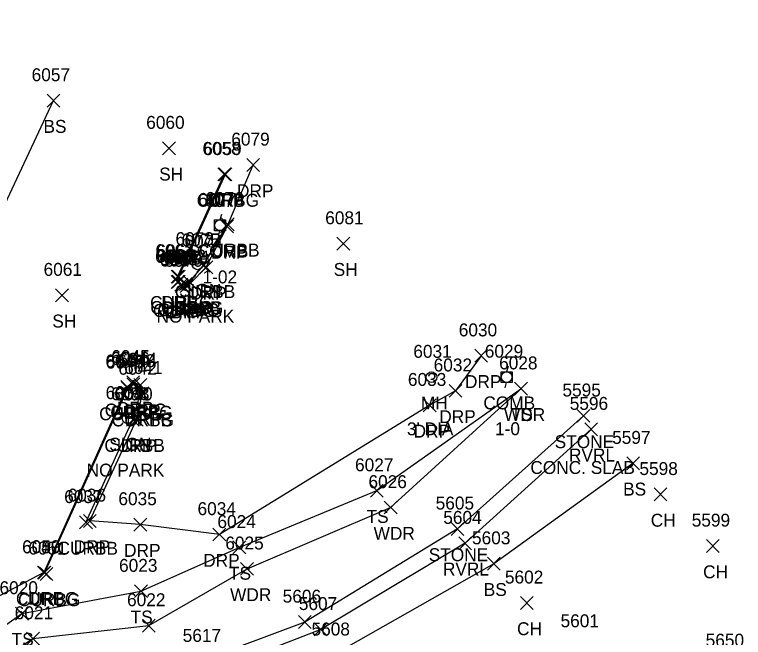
# Model space of a CAD drawing. Extents: x 1618146 to 1620418, y 640749 to 641927.
# Drawn here: x 1620082.5 to 1620195.4, y 641323.6 to 641420.1 of the extents above; entities that cross this region are included whole.
import ezdxf

# ---------------------------------------------------------------- set-up
doc = ezdxf.new("R2010")
doc.units = 0
for name, color, linetype in [('L_A', 7, 'Continuous'), ('L_C', 7, 'Continuous'), ('L_I', 7, 'Continuous'), ('L_TIC', 7, 'Continuous'), ('LASF', 7, 'Continuous'), ('LAWA', 7, 'Continuous'), ('LAWE', 7, 'Continuous'), ('LELB', 7, 'Continuous'), ('R_A', 7, 'Continuous'), ('R_I', 7, 'Continuous'), ('R_TIC', 7, 'Continuous'), ('RC', 7, 'Continuous'), ('RDP', 7, 'Continuous'), ('S_A', 7, 'Continuous'), ('S_C', 7, 'Continuous'), ('S_I', 7, 'Continuous'), ('SSGN', 7, 'Continuous'), ('U_A', 7, 'Continuous'), ('U_C', 7, 'Continuous'), ('U_I', 7, 'Continuous'), ('UP', 7, 'Continuous'), ('UUMH', 7, 'Continuous')]:
    doc.layers.add(name, color=color, linetype=linetype)

msp = doc.modelspace()

# ---------------------------------------------------------------- linework, layer by layer
at = {"layer": 'L_TIC'}
for points in [[(1620087.57, 641405.74), (1620089.57, 641407.74)], [(1620089.57, 641405.74), (1620087.57, 641407.74)], [(1620105.45, 641398.36), (1620107.45, 641400.36)], [(1620107.45, 641398.36), (1620105.45, 641400.36)], [(1620132.48, 641383.59), (1620134.48, 641385.59)], [(1620134.48, 641383.59), (1620132.48, 641385.59)], [(1620088.89, 641375.6), (1620090.89, 641377.6)], [(1620090.89, 641375.6), (1620088.89, 641377.6)], [(1620159.99, 641361.12), (1620161.99, 641363.12)], [(1620161.99, 641361.12), (1620159.99, 641363.12)], [(1620159.99, 641361.12), (1620161.99, 641363.12)], [(1620161.99, 641361.12), (1620159.99, 641363.12)], [(1620169.67, 641356.92), (1620171.67, 641358.92)], [(1620171.67, 641356.92), (1620169.67, 641358.92)], [(1620170.86, 641354.85), (1620172.86, 641356.85)], [(1620172.86, 641354.85), (1620170.86, 641356.85)], [(1620177.37, 641349.58), (1620179.37, 641351.58)], [(1620179.37, 641349.58), (1620177.37, 641351.58)], [(1620137.66, 641345.34), (1620139.66, 641347.34)], [(1620139.66, 641345.34), (1620137.66, 641347.34)], [(1620181.6, 641344.76), (1620183.6, 641346.76)], [(1620183.6, 641344.76), (1620181.6, 641346.76)], [(1620139.8, 641342.73), (1620141.8, 641344.73)], [(1620141.8, 641342.73), (1620139.8, 641344.73)], [(1620150.16, 641339.42), (1620152.16, 641341.42)], [(1620152.16, 641339.42), (1620150.16, 641341.42)], [(1620151.34, 641337.2), (1620153.34, 641339.2)], [(1620153.34, 641337.2), (1620151.34, 641339.2)], [(1620116.34, 641336.55), (1620118.34, 641338.55)], [(1620118.34, 641336.55), (1620116.34, 641338.55)], [(1620189.71, 641336.77), (1620191.71, 641338.77)], [(1620191.71, 641336.77), (1620189.71, 641338.77)], [(1620155.78, 641334.03), (1620157.78, 641336.03)], [(1620157.78, 641334.03), (1620155.78, 641336.03)], [(1620117.56, 641333.23), (1620119.56, 641335.23)], [(1620119.56, 641333.23), (1620117.56, 641335.23)], [(1620101.11, 641329.77), (1620103.11, 641331.77)], [(1620103.11, 641329.77), (1620101.11, 641331.77)], [(1620160.89, 641327.96), (1620162.89, 641329.96)], [(1620162.89, 641327.96), (1620160.89, 641329.96)], [(1620082.67, 641326.31), (1620084.67, 641328.31)], [(1620084.67, 641326.31), (1620082.67, 641328.31)], [(1620126.51, 641325), (1620128.51, 641327)], [(1620128.51, 641325), (1620126.51, 641327)], [(1620102.34, 641324.45), (1620104.34, 641326.45)], [(1620104.34, 641324.45), (1620102.34, 641326.45)], [(1620128.96, 641323.85), (1620130.96, 641325.85)], [(1620130.96, 641323.85), (1620128.96, 641325.85)], [(1620084.38, 641322.43), (1620086.38, 641324.43)], [(1620086.38, 641322.43), (1620084.38, 641324.43)]]:
    msp.add_lwpolyline(points, dxfattribs=at)
at = {"layer": 'LASF'}
msp.add_lwpolyline([(1620170.67, 641357.92), (1620151.16, 641340.42), (1620127.51, 641326), (1620111.32, 641319.92), (1620095.61, 641318.35), (1620069.66, 641305.45), (1620049.44, 641298.08), (1620030.95, 641301.74), (1620009.21, 641303.41), (1619992.86, 641294.85), (1619980.43, 641291.88)], dxfattribs=at)
at = {"layer": 'LAWA'}
msp.add_lwpolyline([(1620069.66, 641305.45), (1620057.71, 641308.73), (1620064.58, 641309.15), (1620072.37, 641314.79), (1620085.38, 641323.43), (1620103.34, 641325.45), (1620118.56, 641334.23), (1620140.8, 641343.73), (1620160.99, 641362.12)], dxfattribs=at)
at = {"layer": 'LAWE'}
msp.add_lwpolyline([(1620171.86, 641355.85), (1620152.34, 641338.2), (1620129.96, 641324.85), (1620111.93, 641317.84), (1620096.25, 641317.33), (1620096.2, 641316.75), (1620094.16, 641317.06), (1620094.28, 641315.29), (1620071.24, 641300.59), (1620050.39, 641293.63), (1620030.98, 641297.72), (1620009.6, 641296.43), (1619997.99, 641289.69), (1619969.13, 641278.68), (1619952.14, 641274.33), (1619935.16, 641265.54), (1619913.67, 641252.74)], dxfattribs=at)
at = {"layer": 'LELB'}
for points in [[(1620044.68, 641320.25), (1620056.71, 641339.91), (1620068.51, 641363.99), (1620079.85, 641388.24), (1620088.57, 641406.74)], [(1619998.22, 641324.34), (1620000.03, 641323.74), (1620010.58, 641317.4), (1620012.2, 641312.35), (1620021.85, 641309.22), (1620032.97, 641306.95), (1620046.8, 641309.77), (1620057.71, 641308.73), (1620071.27, 641318.53), (1620083.67, 641327.31), (1620102.11, 641330.77), (1620117.34, 641337.55), (1620138.66, 641346.34), (1620160.99, 641362.12)], [(1620178.37, 641350.58), (1620156.78, 641335.03), (1620131.93, 641320.91), (1620116.04, 641312.86), (1620100.67, 641308.52)]]:
    msp.add_lwpolyline(points, dxfattribs=at)
at = {"layer": 'R_TIC'}
for points in [[(1620118.5, 641395.77), (1620120.5, 641397.77)], [(1620120.5, 641395.77), (1620118.5, 641397.77)], [(1620114.02, 641394.33), (1620116.02, 641396.33)], [(1620116.02, 641394.33), (1620114.02, 641396.33)], [(1620114.17, 641394.3), (1620116.17, 641396.3)], [(1620116.17, 641394.3), (1620114.17, 641396.3)], [(1620114.46, 641386.26), (1620116.46, 641388.26)], [(1620116.46, 641386.26), (1620114.46, 641388.26)], [(1620114.55, 641386.58), (1620116.55, 641388.58)], [(1620116.55, 641386.58), (1620114.55, 641388.58)], [(1620110.77, 641380.16), (1620112.77, 641382.16)], [(1620112.77, 641380.16), (1620110.77, 641382.16)], [(1620111.24, 641379.92), (1620113.24, 641381.92)], [(1620113.24, 641379.92), (1620111.24, 641381.92)], [(1620106.77, 641378.49), (1620108.77, 641380.49)], [(1620108.77, 641378.49), (1620106.77, 641380.49)], [(1620106.95, 641378.46), (1620108.95, 641380.46)], [(1620108.95, 641378.46), (1620106.95, 641380.46)], [(1620106.97, 641377.7), (1620108.97, 641379.7)], [(1620108.97, 641377.7), (1620106.97, 641379.7)], [(1620108.63, 641377.65), (1620110.63, 641379.65)], [(1620110.63, 641377.65), (1620108.63, 641379.65)], [(1620108.63, 641377.65), (1620110.63, 641379.65)], [(1620110.63, 641377.65), (1620108.63, 641379.65)], [(1620106.8, 641377.63), (1620108.8, 641379.63)], [(1620108.8, 641377.63), (1620106.8, 641379.63)], [(1620107.38, 641377.24), (1620109.38, 641379.24)], [(1620109.38, 641377.24), (1620107.38, 641379.24)], [(1620107.47, 641377.04), (1620109.47, 641379.04)], [(1620109.47, 641377.04), (1620107.47, 641379.04)], [(1620108.07, 641377.35), (1620110.07, 641379.35)], [(1620110.07, 641377.35), (1620108.07, 641379.35)], [(1620108.21, 641377.01), (1620110.21, 641379.01)], [(1620110.21, 641377.01), (1620108.21, 641379.01)], [(1620108.8, 641377.49), (1620110.8, 641379.49)], [(1620110.8, 641377.49), (1620108.8, 641379.49)], [(1620153.82, 641366.23), (1620155.82, 641368.23)], [(1620155.82, 641366.23), (1620153.82, 641368.23)], [(1620099.91, 641362.1), (1620101.91, 641364.1)], [(1620101.91, 641362.1), (1620099.91, 641364.1)], [(1620099, 641361.41), (1620101, 641363.41)], [(1620101, 641361.41), (1620099, 641363.41)], [(1620099.06, 641361.24), (1620101.06, 641363.24)], [(1620101.06, 641361.24), (1620099.06, 641363.24)], [(1620099.92, 641361.82), (1620101.92, 641363.82)], [(1620101.92, 641361.82), (1620099.92, 641363.82)], [(1620100.78, 641361.46), (1620102.78, 641363.46)], [(1620102.78, 641361.46), (1620100.78, 641363.46)], [(1620101.03, 641361.68), (1620103.03, 641363.68)], [(1620103.03, 641361.68), (1620101.03, 641363.68)], [(1620149.85, 641360.8), (1620151.85, 641362.8)], [(1620151.85, 641360.8), (1620149.85, 641362.8)], [(1620101, 641360.29), (1620103, 641362.29)], [(1620103, 641360.29), (1620101, 641362.29)], [(1620101, 641360.29), (1620103, 641362.29)], [(1620103, 641360.29), (1620101, 641362.29)], [(1620101.33, 641360.4), (1620103.33, 641362.4)], [(1620103.33, 641360.4), (1620101.33, 641362.4)], [(1620145.86, 641358.56), (1620147.86, 641360.56)], [(1620147.86, 641358.56), (1620145.86, 641360.56)], [(1620099.86, 641356.34), (1620101.86, 641358.34)], [(1620101.86, 641356.34), (1620099.86, 641358.34)], [(1620100.45, 641356.31), (1620102.45, 641358.31)], [(1620102.45, 641356.31), (1620100.45, 641358.31)], [(1620092.6, 641340.42), (1620094.6, 641342.42)], [(1620094.6, 641340.42), (1620092.6, 641342.42)], [(1620093.2, 641340.65), (1620095.2, 641342.65)], [(1620095.2, 641340.65), (1620093.2, 641342.65)], [(1620101.01, 641340.09), (1620103.01, 641342.09)], [(1620103.01, 641340.09), (1620101.01, 641342.09)], [(1620113.27, 641338.55), (1620115.27, 641340.55)], [(1620115.27, 641338.55), (1620113.27, 641340.55)], [(1620086.09, 641332.66), (1620088.09, 641334.66)], [(1620088.09, 641332.66), (1620086.09, 641334.66)], [(1620086.17, 641332.63), (1620088.17, 641334.63)], [(1620088.17, 641332.63), (1620086.17, 641334.63)], [(1620086.48, 641332.45), (1620088.48, 641334.45)], [(1620088.48, 641332.45), (1620086.48, 641334.45)]]:
    msp.add_lwpolyline(points, dxfattribs=at)
at = {"layer": 'RC'}
for points in [[(1620115.17, 641395.3), (1620107.95, 641379.46), (1620107.97, 641378.7), (1620108.38, 641378.24), (1620109.07, 641378.35), (1620109.63, 641378.65)], [(1620109.63, 641378.65), (1620111.77, 641381.16), (1620115.55, 641387.58)], [(1620102, 641361.29), (1620101.78, 641362.46), (1620100.92, 641362.82), (1620100.06, 641362.24), (1620087.17, 641333.63), (1620087.48, 641333.45)], [(1620093.6, 641341.42), (1620100.86, 641357.34), (1620102, 641361.29)]]:
    msp.add_lwpolyline(points, dxfattribs=at)
at = {"layer": 'RDP'}
for points in [[(1620154.82, 641367.23), (1620150.85, 641361.8), (1620146.86, 641359.56), (1620114.27, 641339.55), (1620102.01, 641341.09), (1620094.2, 641341.65), (1620101.45, 641357.31), (1620102.33, 641361.4), (1620102.03, 641362.68), (1620100.91, 641363.1), (1620100, 641362.41), (1620087.09, 641333.66), (1620057.86, 641318.28), (1620044.68, 641320.25), (1620026.69, 641324.52), (1620013.64, 641332.89), (1620019.29, 641346.64), (1620028.94, 641364.44), (1620041.85, 641389.16), (1620058.65, 641420.05)], [(1620115.02, 641395.33), (1620107.77, 641379.49), (1620107.8, 641378.63), (1620108.47, 641378.04), (1620109.21, 641378.01), (1620109.8, 641378.49), (1620112.24, 641380.92), (1620115.46, 641387.26), (1620119.5, 641396.77)]]:
    msp.add_lwpolyline(points, dxfattribs=at)
at = {"layer": 'SSGN'}
for p, q in [((1620109.23, 641382.21), (1620112.57, 641382.21)), ((1620110.88, 641381.38), (1620110.88, 641381.38)), ((1620098.41, 641358.38), (1620101.74, 641358.38)), ((1620100.05, 641357.55), (1620100.05, 641357.55))]:
    msp.add_line(p, q, dxfattribs=at)
for centre in [(1620110.88, 641381.38), (1620100.05, 641357.55)]:
    msp.add_circle(centre, 0.833, dxfattribs=at)
at = {"layer": 'UP'}
for p, q in [((1620114.61, 641389.09), (1620114.36, 641388.26)), ((1620113.52, 641386.59), (1620113.52, 641388.26)), ((1620113.52, 641388.26), (1620115.19, 641388.26)), ((1620115.19, 641388.26), (1620115.19, 641386.59)), ((1620115.19, 641386.59), (1620113.52, 641386.59)), ((1620114.11, 641385.76), (1620114.36, 641386.59)), ((1620114.36, 641387.43), (1620114.36, 641387.43)), ((1620159.02, 641365.59), (1620158.77, 641364.76)), ((1620157.94, 641363.09), (1620157.94, 641364.76)), ((1620157.94, 641364.76), (1620159.6, 641364.76)), ((1620158.77, 641363.93), (1620158.77, 641363.93)), ((1620159.6, 641364.76), (1620159.6, 641363.09)), ((1620159.6, 641363.09), (1620157.94, 641363.09)), ((1620158.52, 641362.26), (1620158.77, 641363.09))]:
    msp.add_line(p, q, dxfattribs=at)
for centre in [(1620114.36, 641387.43), (1620158.77, 641363.93)]:
    msp.add_circle(centre, 0.833, dxfattribs=at)
at = {"layer": 'UUMH'}
for p, q in [((1620147.13, 641363.91), (1620147.13, 641363.91)), ((1620147.96, 641363.91), (1620147.96, 641363.91))]:
    msp.add_line(p, q, dxfattribs=at)
msp.add_circle((1620147.13, 641363.91), 0.833, dxfattribs=at)

# ---------------------------------------------------------------- texts
at = {"layer": 'L_A'}
for s, p in [('BS', (1620087.01, 641401.74)), ('SH', (1620104.94, 641394.36)), ('SH', (1620131.97, 641379.59)), ('SH', (1620088.38, 641371.6)), ('WDR', (1620158.35, 641357.12)), ('TS', (1620159.4, 641357.12)), ('STONE', (1620166.21, 641352.92)), ('RVRL', (1620168.43, 641350.85)), ('BS', (1620176.81, 641345.58)), ('TS', (1620137.07, 641341.34)), ('CH', (1620181.09, 641340.76)), ('WDR', (1620138.16, 641338.73)), ('STONE', (1620146.7, 641335.42)), ('TS', (1620115.75, 641332.55)), ('RVRL', (1620148.9, 641333.2)), ('CH', (1620189.2, 641332.77)), ('WDR', (1620115.92, 641329.23)), ('BS', (1620155.22, 641330.03)), ('TS', (1620100.52, 641325.77)), ('CH', (1620160.38, 641323.96)), ('TS', (1620082.08, 641322.31))]:
    msp.add_text(s, height=2, dxfattribs=at).set_placement(p)
at = {"layer": 'L_C'}
msp.add_text('CONC. SLAB', height=2, dxfattribs=at).set_placement((1620162.44, 641348.92))
at = {"layer": 'L_I'}
for s, p in [('6057', (1620085.18, 641409.74)), ('6060', (1620102.93, 641402.36)), ('6081', (1620130.66, 641387.59)), ('6061', (1620087.03, 641379.6)), ('6028', (1620157.6, 641365.12)), ('6028', (1620157.6, 641365.12)), ('5595', (1620167.41, 641360.92)), ('5596', (1620168.54, 641358.85)), ('5597', (1620175.11, 641353.58)), ('6027', (1620135.28, 641349.34)), ('5598', (1620179.34, 641348.76)), ('6026', (1620137.36, 641346.73)), ('5605', (1620147.77, 641343.42)), ('6024', (1620113.96, 641340.55)), ('5604', (1620148.95, 641341.2)), ('5599', (1620187.44, 641340.77)), ('6025', (1620115.18, 641337.23)), ('5603', (1620153.4, 641338.03)), ('6023', (1620098.72, 641333.77)), ('5602', (1620158.5, 641331.96)), ('6020', (1620080.2, 641330.31)), ('6022', (1620099.96, 641328.45)), ('5606', (1620124.07, 641329)), ('5607', (1620126.57, 641327.85)), ('6021', (1620082.56, 641326.43)), ('5601', (1620167.12, 641325.19)), ('5608', (1620128.54, 641323.91)), ('5617', (1620108.58, 641322.92)), ('5650', (1620189.6, 641322.19))]:
    msp.add_text(s, height=2, dxfattribs=at).set_placement(p)
at = {"layer": 'R_A'}
for s, p in [('DRP', (1620116.99, 641391.77)), ('CURBG', (1620110.75, 641390.3)), ('DRP', (1620112.51, 641390.33)), ('CURBB', (1620111.13, 641382.58)), ('DRP', (1620112.95, 641382.26)), ('CURBB', (1620107.36, 641376.16)), ('DRP', (1620109.73, 641375.92)), ('CURBG', (1620103.53, 641374.46)), ('DRP', (1620105.26, 641374.49)), ('CURBG', (1620103.56, 641373.7)), ('CURBG', (1620103.97, 641373.24)), ('CURBG', (1620104.65, 641373.35)), ('CURBG', (1620105.21, 641373.65)), ('CURBB', (1620105.21, 641373.65)), ('DRP', (1620105.29, 641373.63)), ('DRP', (1620107.29, 641373.49)), ('DRP', (1620105.96, 641373.04)), ('DRP', (1620106.7, 641373.01)), ('DRP', (1620152.31, 641362.23)), ('CURBG', (1620096.5, 641357.82)), ('CURBG', (1620097.36, 641357.46)), ('DRP', (1620097.49, 641357.41)), ('DRP', (1620098.39, 641358.1)), ('DRP', (1620099.52, 641357.68)), ('CURBG', (1620095.64, 641357.24)), ('CURBG', (1620097.58, 641356.29)), ('CURBB', (1620097.58, 641356.29)), ('DRP', (1620099.82, 641356.4)), ('DRP', (1620148.33, 641356.8)), ('DRP', (1620144.35, 641354.56)), ('CURBB', (1620096.45, 641352.34)), ('DRP', (1620098.94, 641352.31)), ('CURBB', (1620089.19, 641336.42)), ('DRP', (1620091.69, 641336.65)), ('DRP', (1620099.5, 641336.09)), ('DRP', (1620111.76, 641334.55)), ('CURBG', (1620082.75, 641328.63)), ('CURBG', (1620083.06, 641328.45)), ('DRP', (1620084.58, 641328.66))]:
    msp.add_text(s, height=2, dxfattribs=at).set_placement(p)
at = {"layer": 'R_I'}
for s, p in [('6079', (1620116.11, 641399.77)), ('6058', (1620111.64, 641398.33)), ('6059', (1620111.77, 641398.3)), ('6078', (1620112.07, 641390.26)), ('6076', (1620112.1, 641390.58)), ('6075', (1620108.39, 641384.16)), ('6074', (1620108.86, 641383.92)), ('6063', (1620104.34, 641382.49)), ('6064', (1620104.51, 641382.46)), ('6066', (1620104.31, 641381.63)), ('6065', (1620104.54, 641381.7)), ('6068', (1620104.95, 641381.24)), ('6067', (1620105.04, 641381.04)), ('6069', (1620105.63, 641381.35)), ('6070', (1620105.74, 641381.01)), ('6072', (1620106.24, 641381.65)), ('6072', (1620106.24, 641381.65)), ('6071', (1620106.98, 641381.49)), ('6030', (1620151.35, 641370.23)), ('6048', (1620096.61, 641365.41)), ('6047', (1620096.67, 641365.24)), ('6046', (1620097.48, 641365.82)), ('6045', (1620097.52, 641366.1)), ('6043', (1620098.39, 641365.46)), ('6044', (1620098.64, 641365.68)), ('6042', (1620098.61, 641364.29)), ('6042', (1620098.61, 641364.29)), ('6041', (1620099.51, 641364.4)), ('6032', (1620147.46, 641364.8)), ('6033', (1620143.47, 641362.56)), ('6038', (1620097.48, 641360.34)), ('6040', (1620097.98, 641360.31)), ('6037', (1620090.22, 641344.42)), ('6036', (1620090.76, 641344.65)), ('6035', (1620098.62, 641344.09)), ('6034', (1620110.88, 641342.55)), ('6050', (1620083.7, 641336.63)), ('6049', (1620083.7, 641336.66)), ('6051', (1620084.66, 641336.45))]:
    msp.add_text(s, height=2, dxfattribs=at).set_placement(p)
at = {"layer": 'S_A'}
for p in [(1620108.02, 641376.36), (1620097.19, 641352.52)]:
    msp.add_text('SIGN', height=2, dxfattribs=at).set_placement(p)
at = {"layer": 'S_C'}
for p in [(1620104.53, 641372.36), (1620093.7, 641348.52)]:
    msp.add_text('NO PARK', height=2, dxfattribs=at).set_placement(p)
at = {"layer": 'S_I'}
for s, p in [('6073', (1620107.47, 641384.36)), ('6039', (1620096.64, 641360.52))]:
    msp.add_text(s, height=2, dxfattribs=at).set_placement(p)
at = {"layer": 'U_A'}
for s, p in [('COMB', (1620110.74, 641382.43)), ('MH', (1620145.49, 641358.91)), ('COMB', (1620155.16, 641358.93))]:
    msp.add_text(s, height=2, dxfattribs=at).set_placement(p)
at = {"layer": 'U_C'}
for s, p in [('1-02', (1620111.66, 641378.43)), ("3' DIA", (1620143.32, 641354.91)), ('1-0', (1620156.97, 641354.93))]:
    msp.add_text(s, height=2, dxfattribs=at).set_placement(p)
at = {"layer": 'U_I'}
for s, p in [('6077', (1620110.97, 641390.43)), ('6031', (1620144.31, 641366.91)), ('6029', (1620155.38, 641366.93))]:
    msp.add_text(s, height=2, dxfattribs=at).set_placement(p)

doc.saveas('drawing.dxf')
